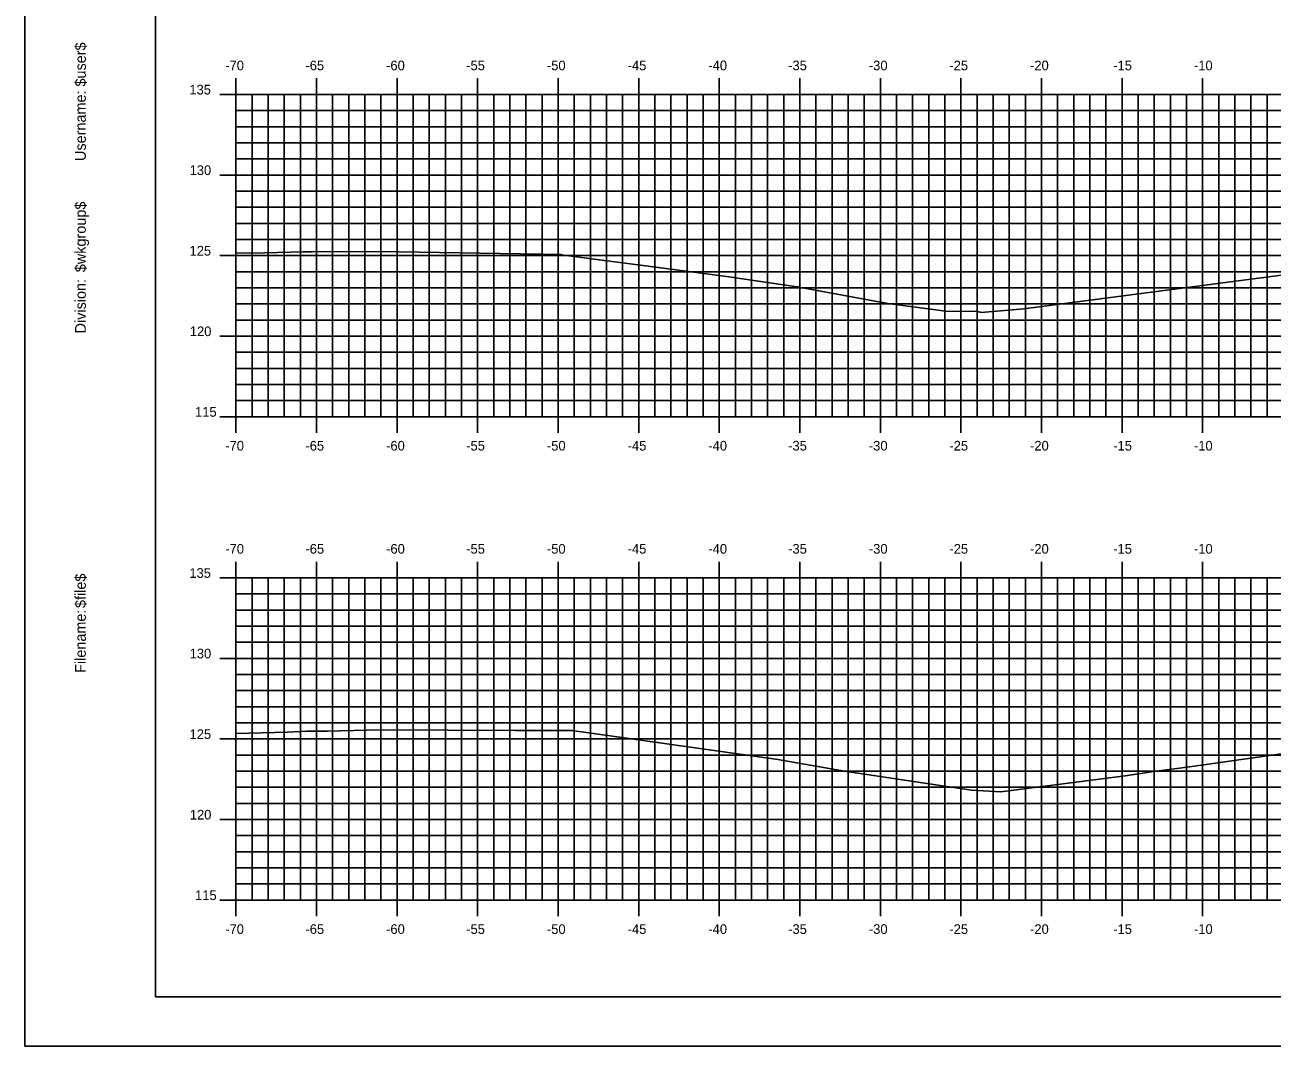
# Model space of a CAD drawing. Extents: x 851960 to 852132, y 365624 to 365734.
# Drawn here: x 851960.2 to 852037.6, y 365624 to 365687.3 of the extents above; entities that cross this region are included whole.
import ezdxf

# ---------------------------------------------------------------- set-up
doc = ezdxf.new("R2010")
doc.units = 0
for name, color, linetype in [('BORDER', 7, 'Continuous'), ('H_V ANNOTATION', 7, 'Continuous'), ('M_Roadway_Centerline', 7, 'Continuous'), ('MAJOR', 7, 'Continuous'), ('MINOR', 7, 'Continuous'), ('PLOT BOUNDARY', 7, 'Continuous'), ('S_Roadway_Centerline', 7, 'Continuous')]:
    doc.layers.add(name, color=color, linetype=linetype)

msp = doc.modelspace()

# ---------------------------------------------------------------- linework, layer by layer
at = {"layer": 'BORDER'}
msp.add_lwpolyline([(851968.279, 365627.027), (852128.279, 365627.027), (852128.279, 365732.027), (851968.279, 365732.027)], close=True, dxfattribs=at)
at = {"layer": 'MAJOR'}
for p, q in [((851973.279, 365684.029), (851973.279, 365683.027)), ((851978.279, 365684.029), (851978.279, 365683.027)), ((851983.279, 365684.029), (851983.279, 365683.027)), ((851988.279, 365684.029), (851988.279, 365683.027)), ((851993.279, 365684.029), (851993.279, 365683.027)), ((851998.279, 365684.029), (851998.279, 365683.027)), ((852003.279, 365684.029), (852003.279, 365683.027)), ((852008.279, 365684.029), (852008.279, 365683.027)), ((852013.279, 365684.029), (852013.279, 365683.027)), ((852018.279, 365684.029), (852018.279, 365683.027)), ((852023.279, 365684.029), (852023.279, 365683.027)), ((852028.279, 365684.029), (852028.279, 365683.027)), ((852033.279, 365684.029), (852033.279, 365683.027)), ((851972.277, 365683.027), (851973.279, 365683.027)), ((851973.279, 365683.027), (852113.279, 365683.027)), ((851973.279, 365663.027), (851973.279, 365683.027)), ((851973.279, 365663.027), (851973.279, 365683.027)), ((851973.279, 365683.027), (852113.279, 365683.027)), ((851978.279, 365663.027), (851978.279, 365683.027)), ((851983.279, 365663.027), (851983.279, 365683.027)), ((851988.279, 365663.027), (851988.279, 365683.027)), ((851993.279, 365663.027), (851993.279, 365683.027)), ((851998.279, 365663.027), (851998.279, 365683.027)), ((852003.279, 365663.027), (852003.279, 365683.027)), ((852008.279, 365663.027), (852008.279, 365683.027)), ((852013.279, 365663.027), (852013.279, 365683.027)), ((852018.279, 365663.027), (852018.279, 365683.027)), ((852023.279, 365663.027), (852023.279, 365683.027)), ((852028.279, 365663.027), (852028.279, 365683.027)), ((852033.279, 365663.027), (852033.279, 365683.027)), ((851972.277, 365678.027), (851973.279, 365678.027)), ((851973.279, 365678.027), (852113.279, 365678.027)), ((851972.277, 365673.027), (851973.279, 365673.027)), ((851973.279, 365673.027), (852113.279, 365673.027)), ((851972.277, 365668.027), (851973.279, 365668.027)), ((851973.279, 365668.027), (852113.279, 365668.027)), ((851972.277, 365663.027), (851973.279, 365663.027)), ((851973.279, 365663.027), (852113.279, 365663.027)), ((851973.279, 365663.027), (852113.279, 365663.027)), ((851973.279, 365662.025), (851973.279, 365663.027)), ((851978.279, 365662.025), (851978.279, 365663.027)), ((851983.279, 365662.025), (851983.279, 365663.027)), ((851988.279, 365662.025), (851988.279, 365663.027)), ((851993.279, 365662.025), (851993.279, 365663.027)), ((851998.279, 365662.025), (851998.279, 365663.027)), ((852003.279, 365662.025), (852003.279, 365663.027)), ((852008.279, 365662.025), (852008.279, 365663.027)), ((852013.279, 365662.025), (852013.279, 365663.027)), ((852018.279, 365662.025), (852018.279, 365663.027)), ((852023.279, 365662.025), (852023.279, 365663.027)), ((852028.279, 365662.025), (852028.279, 365663.027)), ((852033.279, 365662.025), (852033.279, 365663.027)), ((851973.279, 365654.029), (851973.279, 365653.027)), ((851978.279, 365654.029), (851978.279, 365653.027)), ((851983.279, 365654.029), (851983.279, 365653.027)), ((851988.279, 365654.029), (851988.279, 365653.027)), ((851993.279, 365654.029), (851993.279, 365653.027)), ((851998.279, 365654.029), (851998.279, 365653.027)), ((852003.279, 365654.029), (852003.279, 365653.027)), ((852008.279, 365654.029), (852008.279, 365653.027)), ((852013.279, 365654.029), (852013.279, 365653.027)), ((852018.279, 365654.029), (852018.279, 365653.027)), ((852023.279, 365654.029), (852023.279, 365653.027)), ((852028.279, 365654.029), (852028.279, 365653.027)), ((852033.279, 365654.029), (852033.279, 365653.027)), ((851972.277, 365653.027), (851973.279, 365653.027)), ((851973.279, 365653.027), (852113.279, 365653.027)), ((851973.279, 365633.027), (851973.279, 365653.027)), ((851973.279, 365633.027), (851973.279, 365653.027)), ((851973.279, 365653.027), (852113.279, 365653.027)), ((851978.279, 365633.027), (851978.279, 365653.027)), ((851983.279, 365633.027), (851983.279, 365653.027)), ((851988.279, 365633.027), (851988.279, 365653.027)), ((851993.279, 365633.027), (851993.279, 365653.027)), ((851998.279, 365633.027), (851998.279, 365653.027)), ((852003.279, 365633.027), (852003.279, 365653.027)), ((852008.279, 365633.027), (852008.279, 365653.027)), ((852013.279, 365633.027), (852013.279, 365653.027)), ((852018.279, 365633.027), (852018.279, 365653.027)), ((852023.279, 365633.027), (852023.279, 365653.027)), ((852028.279, 365633.027), (852028.279, 365653.027)), ((852033.279, 365633.027), (852033.279, 365653.027)), ((851972.277, 365648.027), (851973.279, 365648.027)), ((851973.279, 365648.027), (852113.279, 365648.027)), ((851972.277, 365643.027), (851973.279, 365643.027)), ((851973.279, 365643.027), (852113.279, 365643.027)), ((851972.277, 365638.027), (851973.279, 365638.027)), ((851973.279, 365638.027), (852113.279, 365638.027)), ((851972.277, 365633.027), (851973.279, 365633.027)), ((851973.279, 365633.027), (852113.279, 365633.027)), ((851973.279, 365633.027), (852113.279, 365633.027)), ((851973.279, 365632.025), (851973.279, 365633.027)), ((851978.279, 365632.025), (851978.279, 365633.027)), ((851983.279, 365632.025), (851983.279, 365633.027)), ((851988.279, 365632.025), (851988.279, 365633.027)), ((851993.279, 365632.025), (851993.279, 365633.027)), ((851998.279, 365632.025), (851998.279, 365633.027)), ((852003.279, 365632.025), (852003.279, 365633.027)), ((852008.279, 365632.025), (852008.279, 365633.027)), ((852013.279, 365632.025), (852013.279, 365633.027)), ((852018.279, 365632.025), (852018.279, 365633.027)), ((852023.279, 365632.025), (852023.279, 365633.027)), ((852028.279, 365632.025), (852028.279, 365633.027)), ((852033.279, 365632.025), (852033.279, 365633.027))]:
    msp.add_line(p, q, dxfattribs=at)
at = {"layer": 'MINOR'}
for p, q in [((851974.279, 365663.027), (851974.279, 365683.027)), ((851975.279, 365663.027), (851975.279, 365683.027)), ((851976.279, 365663.027), (851976.279, 365683.027)), ((851977.279, 365663.027), (851977.279, 365683.027)), ((851979.279, 365663.027), (851979.279, 365683.027)), ((851980.279, 365663.027), (851980.279, 365683.027)), ((851981.279, 365663.027), (851981.279, 365683.027)), ((851982.279, 365663.027), (851982.279, 365683.027)), ((851984.279, 365663.027), (851984.279, 365683.027)), ((851985.279, 365663.027), (851985.279, 365683.027)), ((851986.279, 365663.027), (851986.279, 365683.027)), ((851987.279, 365663.027), (851987.279, 365683.027)), ((851989.279, 365663.027), (851989.279, 365683.027)), ((851990.279, 365663.027), (851990.279, 365683.027)), ((851991.279, 365663.027), (851991.279, 365683.027)), ((851992.279, 365663.027), (851992.279, 365683.027)), ((851994.279, 365663.027), (851994.279, 365683.027)), ((851995.279, 365663.027), (851995.279, 365683.027)), ((851996.279, 365663.027), (851996.279, 365683.027)), ((851997.279, 365663.027), (851997.279, 365683.027)), ((851999.279, 365663.027), (851999.279, 365683.027)), ((852000.279, 365663.027), (852000.279, 365683.027)), ((852001.279, 365663.027), (852001.279, 365683.027)), ((852002.279, 365663.027), (852002.279, 365683.027)), ((852004.279, 365663.027), (852004.279, 365683.027)), ((852005.279, 365663.027), (852005.279, 365683.027)), ((852006.279, 365663.027), (852006.279, 365683.027)), ((852007.279, 365663.027), (852007.279, 365683.027)), ((852009.279, 365663.027), (852009.279, 365683.027)), ((852010.279, 365663.027), (852010.279, 365683.027)), ((852011.279, 365663.027), (852011.279, 365683.027)), ((852012.279, 365663.027), (852012.279, 365683.027)), ((852014.279, 365663.027), (852014.279, 365683.027)), ((852015.279, 365663.027), (852015.279, 365683.027)), ((852016.279, 365663.027), (852016.279, 365683.027)), ((852017.279, 365663.027), (852017.279, 365683.027)), ((852019.279, 365663.027), (852019.279, 365683.027)), ((852020.279, 365663.027), (852020.279, 365683.027)), ((852021.279, 365663.027), (852021.279, 365683.027)), ((852022.279, 365663.027), (852022.279, 365683.027)), ((852024.279, 365663.027), (852024.279, 365683.027)), ((852025.279, 365663.027), (852025.279, 365683.027)), ((852026.279, 365663.027), (852026.279, 365683.027)), ((852027.279, 365663.027), (852027.279, 365683.027)), ((852029.279, 365663.027), (852029.279, 365683.027)), ((852030.279, 365663.027), (852030.279, 365683.027)), ((852031.279, 365663.027), (852031.279, 365683.027)), ((852032.279, 365663.027), (852032.279, 365683.027)), ((852034.279, 365663.027), (852034.279, 365683.027)), ((852035.279, 365663.027), (852035.279, 365683.027)), ((852036.279, 365663.027), (852036.279, 365683.027)), ((852037.279, 365663.027), (852037.279, 365683.027)), ((851973.279, 365682.027), (852113.279, 365682.027)), ((851973.279, 365682.027), (851974.281, 365682.027)), ((851973.279, 365681.027), (852113.279, 365681.027)), ((851973.279, 365681.027), (851974.281, 365681.027)), ((851973.279, 365680.027), (852113.279, 365680.027)), ((851973.279, 365680.027), (851974.281, 365680.027)), ((851973.279, 365679.027), (852113.279, 365679.027)), ((851973.279, 365679.027), (851974.281, 365679.027)), ((851973.279, 365677.027), (852113.279, 365677.027)), ((851973.279, 365677.027), (851974.281, 365677.027)), ((851973.279, 365676.027), (852113.279, 365676.027)), ((851973.279, 365676.027), (851974.281, 365676.027)), ((851973.279, 365675.027), (852113.279, 365675.027)), ((851973.279, 365675.027), (851974.281, 365675.027)), ((851973.279, 365674.027), (852113.279, 365674.027)), ((851973.279, 365674.027), (851974.281, 365674.027)), ((851973.279, 365672.027), (852113.279, 365672.027)), ((851973.279, 365672.027), (851974.281, 365672.027)), ((851973.279, 365671.027), (852113.279, 365671.027)), ((851973.279, 365671.027), (851974.281, 365671.027)), ((851973.279, 365670.027), (852113.279, 365670.027)), ((851973.279, 365670.027), (851974.281, 365670.027)), ((851973.279, 365669.027), (852113.279, 365669.027)), ((851973.279, 365669.027), (851974.281, 365669.027)), ((851973.279, 365667.027), (852113.279, 365667.027)), ((851973.279, 365667.027), (851974.281, 365667.027)), ((851973.279, 365666.027), (852113.279, 365666.027)), ((851973.279, 365666.027), (851974.281, 365666.027)), ((851973.279, 365665.027), (852113.279, 365665.027)), ((851973.279, 365665.027), (851974.281, 365665.027)), ((851973.279, 365664.027), (852113.279, 365664.027)), ((851973.279, 365664.027), (851974.281, 365664.027)), ((851974.279, 365633.027), (851974.279, 365653.027)), ((851975.279, 365633.027), (851975.279, 365653.027)), ((851976.279, 365633.027), (851976.279, 365653.027)), ((851977.279, 365633.027), (851977.279, 365653.027)), ((851979.279, 365633.027), (851979.279, 365653.027)), ((851980.279, 365633.027), (851980.279, 365653.027)), ((851981.279, 365633.027), (851981.279, 365653.027)), ((851982.279, 365633.027), (851982.279, 365653.027)), ((851984.279, 365633.027), (851984.279, 365653.027)), ((851985.279, 365633.027), (851985.279, 365653.027)), ((851986.279, 365633.027), (851986.279, 365653.027)), ((851987.279, 365633.027), (851987.279, 365653.027)), ((851989.279, 365633.027), (851989.279, 365653.027)), ((851990.279, 365633.027), (851990.279, 365653.027)), ((851991.279, 365633.027), (851991.279, 365653.027)), ((851992.279, 365633.027), (851992.279, 365653.027)), ((851994.279, 365633.027), (851994.279, 365653.027)), ((851995.279, 365633.027), (851995.279, 365653.027)), ((851996.279, 365633.027), (851996.279, 365653.027)), ((851997.279, 365633.027), (851997.279, 365653.027)), ((851999.279, 365633.027), (851999.279, 365653.027)), ((852000.279, 365633.027), (852000.279, 365653.027)), ((852001.279, 365633.027), (852001.279, 365653.027)), ((852002.279, 365633.027), (852002.279, 365653.027)), ((852004.279, 365633.027), (852004.279, 365653.027)), ((852005.279, 365633.027), (852005.279, 365653.027)), ((852006.279, 365633.027), (852006.279, 365653.027)), ((852007.279, 365633.027), (852007.279, 365653.027)), ((852009.279, 365633.027), (852009.279, 365653.027)), ((852010.279, 365633.027), (852010.279, 365653.027)), ((852011.279, 365633.027), (852011.279, 365653.027)), ((852012.279, 365633.027), (852012.279, 365653.027)), ((852014.279, 365633.027), (852014.279, 365653.027)), ((852015.279, 365633.027), (852015.279, 365653.027)), ((852016.279, 365633.027), (852016.279, 365653.027)), ((852017.279, 365633.027), (852017.279, 365653.027)), ((852019.279, 365633.027), (852019.279, 365653.027)), ((852020.279, 365633.027), (852020.279, 365653.027)), ((852021.279, 365633.027), (852021.279, 365653.027)), ((852022.279, 365633.027), (852022.279, 365653.027)), ((852024.279, 365633.027), (852024.279, 365653.027)), ((852025.279, 365633.027), (852025.279, 365653.027)), ((852026.279, 365633.027), (852026.279, 365653.027)), ((852027.279, 365633.027), (852027.279, 365653.027)), ((852029.279, 365633.027), (852029.279, 365653.027)), ((852030.279, 365633.027), (852030.279, 365653.027)), ((852031.279, 365633.027), (852031.279, 365653.027)), ((852032.279, 365633.027), (852032.279, 365653.027)), ((852034.279, 365633.027), (852034.279, 365653.027)), ((852035.279, 365633.027), (852035.279, 365653.027)), ((852036.279, 365633.027), (852036.279, 365653.027)), ((852037.279, 365633.027), (852037.279, 365653.027)), ((851973.279, 365652.027), (852113.279, 365652.027)), ((851973.279, 365652.027), (851974.281, 365652.027)), ((851973.279, 365651.027), (852113.279, 365651.027)), ((851973.279, 365651.027), (851974.281, 365651.027)), ((851973.279, 365650.027), (852113.279, 365650.027)), ((851973.279, 365650.027), (851974.281, 365650.027)), ((851973.279, 365649.027), (852113.279, 365649.027)), ((851973.279, 365649.027), (851974.281, 365649.027)), ((851973.279, 365647.027), (852113.279, 365647.027)), ((851973.279, 365647.027), (851974.281, 365647.027)), ((851973.279, 365646.027), (852113.279, 365646.027)), ((851973.279, 365646.027), (851974.281, 365646.027)), ((851973.279, 365645.027), (852113.279, 365645.027)), ((851973.279, 365645.027), (851974.281, 365645.027)), ((851973.279, 365644.027), (852113.279, 365644.027)), ((851973.279, 365644.027), (851974.281, 365644.027)), ((851973.279, 365642.027), (852113.279, 365642.027)), ((851973.279, 365642.027), (851974.281, 365642.027)), ((851973.279, 365641.027), (852113.279, 365641.027)), ((851973.279, 365641.027), (851974.281, 365641.027)), ((851973.279, 365640.027), (852113.279, 365640.027)), ((851973.279, 365640.027), (851974.281, 365640.027)), ((851973.279, 365639.027), (852113.279, 365639.027)), ((851973.279, 365639.027), (851974.281, 365639.027)), ((851973.279, 365637.027), (852113.279, 365637.027)), ((851973.279, 365637.027), (851974.281, 365637.027)), ((851973.279, 365636.027), (852113.279, 365636.027)), ((851973.279, 365636.027), (851974.281, 365636.027)), ((851973.279, 365635.027), (852113.279, 365635.027)), ((851973.279, 365635.027), (851974.281, 365635.027)), ((851973.279, 365634.027), (852113.279, 365634.027)), ((851973.279, 365634.027), (851974.281, 365634.027))]:
    msp.add_line(p, q, dxfattribs=at)
at = {"layer": 'PLOT BOUNDARY'}
msp.add_lwpolyline([(851960.186, 365623.968), (852130.186, 365623.968), (852130.186, 365733.968), (851960.186, 365733.968)], close=True, dxfattribs=at)
at = {"layer": 'S_Roadway_Centerline'}
for points in [[(851973.279, 365673.183), (851975.062, 365673.207), (851977.464, 365673.251), (851978.004, 365673.269), (851983.062, 365673.273), (851983.392, 365673.267), (851993.46, 365673.103), (851993.462, 365673.067), (852001.078, 365672.089), (852003.731, 365671.723), (852008.119, 365671.094), (852013.744, 365670.051), (852017.35, 365669.58), (852019.329, 365669.548), (852019.528, 365669.496), (852022.178, 365669.718), (852039.605, 365672.002)], [(851973.279, 365643.36), (851976.491, 365643.448), (851977.688, 365643.505), (851978.95, 365643.52), (851982.232, 365643.591), (851990.638, 365643.561), (851993.631, 365643.552), (851994.063, 365643.551), (851994.141, 365643.549), (851994.266, 365643.532), (851995.475, 365643.358), (852006.922, 365641.76), (852011.059, 365641.024), (852018.938, 365639.856), (852020.765, 365639.75), (852028.481, 365640.74), (852030.393, 365641.019), (852032.313, 365641.267), (852046.057, 365643.213)]]:
    msp.add_lwpolyline(points, dxfattribs=at)

# ---------------------------------------------------------------- texts
at = {"layer": 'BORDER'}
for s, p in [('$user$', (851963.964, 365683.518)), ('Username:', (851963.964, 365678.895)), ('$wkgroup$', (851963.964, 365671.996)), ('Division:', (851963.964, 365668.193)), ('$file$', (851963.964, 365651.152)), ('Filename:', (851963.964, 365647.125))]:
    msp.add_text(s, height=0.6696, rotation=90, dxfattribs=at).set_placement(p)
at = {"layer": 'H_V ANNOTATION'}
for s, p in [('-70', (851972.62, 365684.527)), ('-65', (851977.596, 365684.527)), ('-60', (851982.604, 365684.527)), ('-55', (851987.575, 365684.527)), ('-50', (851992.583, 365684.527)), ('-45', (851997.596, 365684.527)), ('-40', (852002.604, 365684.527)), ('-35', (852007.559, 365684.527)), ('-30', (852012.567, 365684.527)), ('-25', (852017.564, 365684.527)), ('-20', (852022.572, 365684.527)), ('-15', (852027.736, 365684.527)), ('-10', (852032.744, 365684.527)), ('135', (851970.393, 365683.027)), ('130', (851970.409, 365678.027)), ('125', (851970.403, 365673.027)), ('120', (851970.419, 365668.027)), ('115', (851970.746, 365663.027)), ('-70', (851972.62, 365660.927)), ('-65', (851977.596, 365660.927)), ('-60', (851982.604, 365660.927)), ('-55', (851987.575, 365660.927)), ('-50', (851992.583, 365660.927)), ('-45', (851997.596, 365660.927)), ('-40', (852002.604, 365660.927)), ('-35', (852007.559, 365660.927)), ('-30', (852012.567, 365660.927)), ('-25', (852017.564, 365660.927)), ('-20', (852022.572, 365660.927)), ('-15', (852027.736, 365660.927)), ('-10', (852032.744, 365660.927)), ('-70', (851972.62, 365654.527)), ('-65', (851977.596, 365654.527)), ('-60', (851982.604, 365654.527)), ('-55', (851987.575, 365654.527)), ('-50', (851992.583, 365654.527)), ('-45', (851997.596, 365654.527)), ('-40', (852002.604, 365654.527)), ('-35', (852007.559, 365654.527)), ('-30', (852012.567, 365654.527)), ('-25', (852017.564, 365654.527)), ('-20', (852022.572, 365654.527)), ('-15', (852027.736, 365654.527)), ('-10', (852032.744, 365654.527)), ('135', (851970.393, 365653.027)), ('130', (851970.409, 365648.027)), ('125', (851970.403, 365643.027)), ('120', (851970.419, 365638.027)), ('115', (851970.746, 365633.027)), ('-70', (851972.62, 365630.927)), ('-65', (851977.596, 365630.927)), ('-60', (851982.604, 365630.927)), ('-55', (851987.575, 365630.927)), ('-50', (851992.583, 365630.927)), ('-45', (851997.596, 365630.927)), ('-40', (852002.604, 365630.927)), ('-35', (852007.559, 365630.927)), ('-30', (852012.567, 365630.927)), ('-25', (852017.564, 365630.927)), ('-20', (852022.572, 365630.927)), ('-15', (852027.736, 365630.927)), ('-10', (852032.744, 365630.927))]:
    msp.add_text(s, height=0.6, dxfattribs=at).set_placement(p)
at = {"layer": 'M_Roadway_Centerline'}
for s, p in [('C', (851977.459, 365673.251)), ('L', (851977.464, 365673.244)), ('C', (851977.683, 365643.505)), ('L', (851977.688, 365643.498))]:
    msp.add_text(s, height=0.0146, dxfattribs=at).set_placement(p)
at = {"layer": 'MAJOR'}
for p in [(851973.274, 365663.027), (851973.274, 365633.027)]:
    msp.add_text('-', height=0.006, dxfattribs=at).set_placement(p)

doc.saveas('drawing.dxf')
